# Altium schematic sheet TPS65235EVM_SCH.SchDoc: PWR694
size 431 x 279 mm; Date: Not shown in title block; ApprovedBy: Not shown in title block; CheckedBy: Not shown in title block; Author: Not shown in title block; CompanyName: Not shown in title block; DrawnBy: Junjie Mai; Engineer: Junjie Mai; Organization: Not shown in title block; Address1: Not shown in title block; Address2: Not shown in title block; Address3: Not shown in title block; Address4: Not shown in title block; DocumentNumber: 1; Revision: Use project parameter SCH_Rev; SheetNumber: 1; SheetTotal: 2; PageSetup: Record=PageOptions¦CenterHorizontal=True¦CenterVertical=True¦PrintScale=0.64¦XCorrection=1.00¦YCorrection=1.00¦PrintKind=0¦BorderSize=5000000¦LeftOffset=0¦BottomOffset=0¦Orientation=2¦PaperLength=1000¦PaperWidth=1000¦Scale=100¦PaperSource=15¦PrintQuality=600¦MediaType=1¦DitherType=10¦PrintScaleMode=1¦PaperKind=Letter
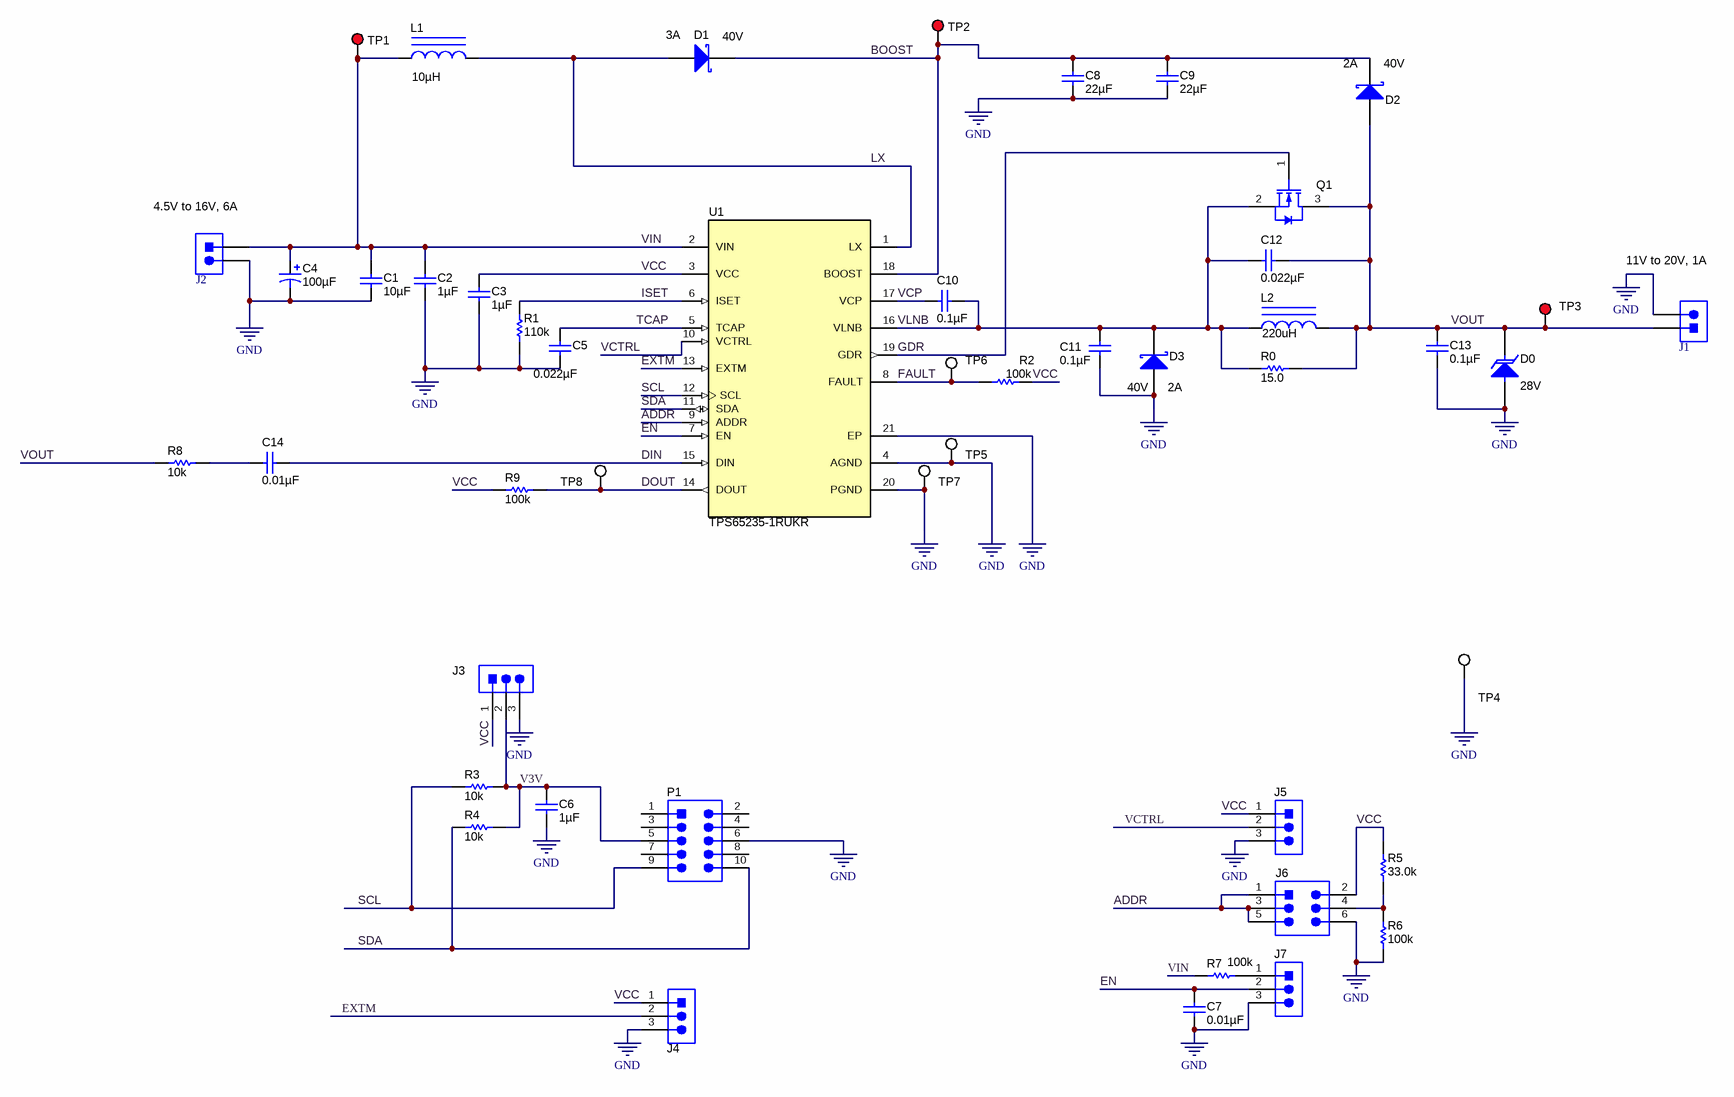
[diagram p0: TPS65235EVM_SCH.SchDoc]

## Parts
C1  ValueDisplayed: 10µF  [1206]  (hidden comment: GRM31CR61E106KA12L)
C2  ValueDisplayed: 1µF  [0603]  (hidden comment: GRM188R61E105KA12D)
C3  ValueDisplayed: 1µF  [0603]  (hidden comment: GRM188R61E105KA12D)
C4  ValueDisplayed: 100µF  [CAPPR250W50D630H1120]  (hidden comment: EEU-EB1E101S)
C5  ValueDisplayed: 0.022µF  [0603]  (hidden comment: GRM188R71H223KA01D)
C6  ValueDisplayed: 1µF  [0603]  (hidden comment: GRM188R61E105KA12D)
C7  ValueDisplayed: 0.01µF  [0603]  (hidden comment: GRM188R71H103KA01D)
C8  ValueDisplayed: 22µF  [1206_180]  (hidden comment: C3216X5R1V226M160AC)
C9  ValueDisplayed: 22µF  [1206_180]  (hidden comment: C3216X5R1V226M160AC)
C10  ValueDisplayed: 0.1µF  [0603]  (hidden comment: 0603YC104JAT2A)
C11  ValueDisplayed: 0.1µF  [0603]  (hidden comment: GRM188R71H104KA93D)
C12  ValueDisplayed: 0.022µF  [0603]  (hidden comment: GRM188R71H223KA01D)
C13  ValueDisplayed: 0.1µF  [0603]  (hidden comment: GRM188R71H104KA93D)
C14  ValueDisplayed: 0.01µF  [0603]  (hidden comment: GRM188R71H103KA01D)
D0  value 28V  [SMC]  (hidden comment: SMCJ28A)
D1  value 40V  Value1: 3A  [SMA]  (hidden comment: B340A-13-F)
D2  value 40V  Value1: 2A  [SMA]  (hidden comment: B240A-13-F)
D3  value 40V  Value1: 2A  [SMA]  (hidden comment: B240A-13-F)
J1  ED555/2DS  [TERM_BLK_ED555-2DS]  (value not drawn)
J2  ED555/2DS  [TERM_BLK_ED555-2DS]  (value not drawn)
J3  TSW-103-07-G-S  [TSW-103-07-G-S]  (value not drawn)
J4  TSW-103-07-G-S  [TSW-103-07-G-S]  (value not drawn)
J5  TSW-103-07-G-S  [TSW-103-07-G-S]  (value not drawn)
J6  TSW-103-07-G-D  [TSW-103-07-G-D]  (value not drawn)
J7  TSW-103-07-G-S  [TSW-103-07-G-S]  (value not drawn)
L1  ValueDisplayed: 10µH  [CLF10040]  (hidden comment: CLF10040T-100M)
L2  value 220uH  [SLF12565]  (hidden comment: SLF12565T-221M1R0-PF)
P1  XG4C-1031  [OMRON_XG4C-1031]  (value not drawn)
Q1  SI2316BDS-T1-E3  [SOT-23]  (value not drawn)
R0  ValueDisplayed: 15.0  [1206]  (hidden comment: CRCW120615R0FKEA)
R1  ValueDisplayed: 110k  [0603]  (hidden comment: CRCW0603110KFKEA)
R2  ValueDisplayed: 100k  [0603]  (hidden comment: CRCW0603100KFKEA)
R3  ValueDisplayed: 10k  [0603]  (hidden comment: CRCW060310K0JNEA)
R4  ValueDisplayed: 10k  [0603]  (hidden comment: CRCW060310K0JNEA)
R5  ValueDisplayed: 33.0k  [0603]  (hidden comment: CRCW060333K0FKEA)
R6  ValueDisplayed: 100k  [0603]  (hidden comment: CRCW0603100KFKEA)
R7  ValueDisplayed: 100k  [0603]  (hidden comment: CRCW0603100KFKEA)
R8  ValueDisplayed: 10k  [0603]  (hidden comment: CRCW060310K0JNEA)
R9  ValueDisplayed: 100k  [0603]  (hidden comment: CRCW0603100KFKEA)
TP1  5010  [Keystone5010]  (value not drawn)
TP2  5010  [Keystone5010]  (value not drawn)
TP3  5010  [Keystone5010]  (value not drawn)
TP4  5012  [Keystone5012]  (value not drawn)
TP5  5012  [Keystone5012]  (value not drawn)
TP6  5012  [Keystone5012]  (value not drawn)
TP7  5012  [Keystone5012]  (value not drawn)
TP8  5012  [Keystone5012]  (value not drawn)
U1  TPS65235-1RUKR  [RUK0020B]

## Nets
GND: C1.2 C2.2 C3.2 C4.2(-) C5.1 C6.2 C7.2 C8.2 C9.2 C11.2 C13.2 D0.2(A) D3.2(A) J1.2 J2.2 J3.3 J4.3 J5.3 J6.6 J7.3 P1.6 R1.1 R6.1 TP4.1 TP5.1 TP7.1 U1.4(AGND) U1.20(PGND) U1.21(EP)
ADDR: J6.1 J6.3 J6.5 U1.9(ADDR)
BOOST: C8.1 C9.1 D1.1(K) D2.1(K) TP2.1 U1.18(BOOST)
DIN: C14.1 U1.15(DIN)
DOUT: R9.2 TP8.1 U1.14(DOUT)
EN: C7.1 J7.2 U1.7(EN)
EXTM: J4.2 U1.13(EXTM)
FAULT: R2.1 TP6.1 U1.8(FAULT)
GDR: Q1.1(G) U1.19(GDR)
ISET: R1.2 U1.6(ISET)
LX: D1.2(A) L1.2 U1.1(LX)
SCL: P1.9 R3.2 U1.12(SCL)
SDA: P1.10 R4.2 U1.11(SDA)
TCAP: C5.2 U1.5(TCAP)
V3V: C6.1 J3.2 P1.5 R3.1 R4.1
VCC: C3.1 J3.1 J4.1 J5.1 J6.2 R2.2 R5.2 R9.1 U1.3(VCC)
VCP: C10.1 U1.17(VCP)
VCTRL: J5.2 U1.10(VCTRL)
VIN: C1.1 C2.1 C4.1(+) J2.1 L1.1 R7.2 TP1.1 U1.2(VIN)
VLNB: C10.2 C11.1 C12.1 D3.1(K) L2.1 Q1.2(S) R0.2 U1.16(VLNB)
VOUT: C12.2 C13.1 D0.1(K) D2.2(A) J1.1 L2.2 Q1.3(D) R0.1 R8.2 TP3.1
NetC14_2: C14.2 R8.1
NetJ6_4: J6.4 R5.1 R6.2
NetJ7_1: J7.1 R7.1

Not connected (* = marked no-connect by the designer): P1 1 2 3 4 7 8

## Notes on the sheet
- (near J2) 4.5V to 16V, 6A
- (near J1) 11V to 20V, 1A

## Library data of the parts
C1 = GRM31CR61E106KA12L: CAP, CERM, 10 µF, 25 V, +/- 10%, X5R, 1206; Manufacturer: MuRata; Polarized: N; CompType: Capacitor; Value: 10uF; U/M: EA; Cap_F: 0.00001; Tolerance_%: 10; ESR_ohm: 0.004; Value1: 0.004 ohm; VDC_V: 25; Value2: 25V; TaMin_C: -55; TaMax_C: 85; AEC Category: Q200
C2 C3 C6 = GRM188R61E105KA12D: CAP, CERM, 1 µF, 25 V, +/- 10%, X5R, 0603; Manufacturer: MuRata; Polarized: N; CompType: Capacitor; Value: 1uF; U/M: EA; Cap_F: 0.000001; Tolerance_%: 10; Value1: Unknown; VDC_V: 25; Value2: 25V; TaMin_C: -55; TaMax_C: 85; AEC Category: Q200
C4 = EEU-EB1E101S: CAP, AL, 100 µF, 25 V, +/- 20%, TH; Manufacturer: Panasonic; Polarized: Y; CompType: Capacitor; Value: 100uF; U/M: EA; Cap_F: 0.0001; Tolerance_%: 20; Value1: Unknown; VDC_V: 25; Value2: 25V; IRMS_A: 0.095; TaMin_C: -40; TaMax_C: 105; Cap_Case: Radial 6.3x11.2; AEC Category: Q200; AEC Qualified: N
C5 C12 = GRM188R71H223KA01D: CAP, CERM, 0.022 µF, 50 V, +/- 10%, X7R, 0603; Manufacturer: MuRata; Polarized: N; CompType: Capacitor; Value: 0.022uF; U/M: EA; Cap_F: 0.000000022; Tolerance_%: 10; Value1: Unknown; VDC_V: 50; Value2: 50V; TaMin_C: -55; TaMax_C: 125; AEC Category: Q200
C7 C14 = GRM188R71H103KA01D: CAP, CERM, 0.01 µF, 50 V, +/- 10%, X7R, 0603; Manufacturer: MuRata; Polarized: N; CompType: Capacitor; Value: 0.01uF; U/M: EA; Cap_F: 0.00000001; Tolerance_%: 10; Value1: Unknown; VDC_V: 50; Value2: 50V; TaMin_C: -55; TaMax_C: 125; AEC Category: Q200
C8 C9 = C3216X5R1V226M160AC: CAP, CERM, 22 µF, 35 V, +/- 20%, X5R, 1206; Manufacturer: TDK; Polarized: N; CompType: Capacitor; Value: 22uF; U/M: EA; Cap_F: 0.000022; Tolerance_%: 20; ESR_ohm: 0.002398; Value1: 0.002398 ohm; VDC_V: 35; Value2: 35V; IRMS_A: 4.68507; TaMin_C: -55; TaMax_C: 85; AEC Category: Q200; SizeArea_mm2: 5.12; SizeAreaWB_mm2: 10.92; SizeX_mm: 3.2; SizeY_mm: 1.6; SizeZ_mm: 1.8
C10 = 0603YC104JAT2A: CAP, CERM, 0.1 µF, 16 V, +/- 5%, X7R, 0603; Manufacturer: AVX; Polarized: N; CompType: Capacitor; Value: 0.1uF; U/M: EA; Cap_F: 0.0000001; Tolerance_%: 5; ESR_ohm: 0.039; Value1: 0.039 ohm; VDC_V: 16; Value2: 16V; TaMin_C: -55; TaMax_C: 125; AEC Category: Q200
C11 C13 = GRM188R71H104KA93D: CAP, CERM, 0.1 µF, 50 V, +/- 10%, X7R, 0603; Manufacturer: MuRata; Polarized: N; CompType: Capacitor; Value: 0.1uF; U/M: EA; Cap_F: 0.0000001; Tolerance_%: 10; Value1: Unknown; VDC_V: 50; Value2: 50V; TaMin_C: -55; TaMax_C: 125; AEC Category: Q200
D0 = SMCJ28A: Diode, TVS, Uni, 28 V, 1500 W, SMC; Manufacturer: Fairchild Semiconductor; U/M: EA; Value1: 1500W; Vr_V: 28; Power_W: 1500; AEC Category: Q101
D1 = B340A-13-F: Diode, Schottky, 40 V, 3 A, SMA; Manufacturer: Diodes Inc.; U/M: EA; Vf_V: 0.5; Value2: 0.5V; Io_A: 3; Vr_V: 40; TJmax_C: 125; RJC_CperW: 25; AEC Category: Q101
D2 D3 = B240A-13-F: Diode, Schottky, 40 V, 2 A, SMA; Manufacturer: Diodes Inc.; U/M: EA; Vf_V: 0.5; Value2: 0.5V; Io_A: 2; Vr_V: 40; TJmax_C: 150; RJC_CperW: 20; AEC Category: Q101
J1 J2 = ED555/2DS: Terminal Block, 6A, 3.5mm Pitch, 2-Pos, TH; Manufacturer: On-Shore Technology; SymbolCreator: a0412235; CompType: Connector; U/M: EA
J3-J5 J7 = TSW-103-07-G-S: Header, 100mil, 3x1, Gold, TH; Manufacturer: Samtec; SymbolCreator: a0799628; U/M: EA
J6 = TSW-103-07-G-D: Header, 100mil, 3x2, Gold, TH; Manufacturer: Samtec; SymbolCreator: a0412235; U/M: EA
L1 = CLF10040T-100M: Inductor, Shielded, Ferrite, 10 µH, 4 A, 0.0312 ohm, SMD; Manufacturer: TDK; Value: 10uH; Ind_H: 10.0E-6; Imax_A: 4; Irms: 3.3A @ 30C rise; Isat: 4A @ 10% inductance drop; DCR_ohm: 0.0312; Value2: 4A; AEC Category: Q200
L2 = SLF12565T-221M1R0-PF: Inductor, Shielded, Ferrite, 220 µH, 1.2 A, 0.273 ohm, SMD; Manufacturer: TDK; Ind_H: 220.0E-6; ValueDisplayed: 220µH; Imax_A: 1.2; Irms: 1.2A @ 40C rise; Isat: 1A @ 10% inductance drop; DCR_ohm: 0.273; Value2: 1.2A; AEC Category: Q200
P1 = XG4C-1031: Header (shrouded), 100mil, 5x2, Gold, TH; Manufacturer: Omron Electronic Components; SymbolCreator: a0412235; U/M: EA
Q1 = SI2316BDS-T1-E3: MOSFET, N-CH, 30 V, 4.5 A, SOT-23; Manufacturer: Vishay-Siliconix; Alternate Manufacturer: None; U/M: EA; ChType: N; Value: 30V; VdsMax_V: 30; Value1: 0.08 ohm; Rdson45_ohm: 0.08; Value2: 3.16 nC; QgTyp_nC: 3.16; Vgs_V: 20; IdsMax_A: 4.5; AEC Category: Q101
R0 = CRCW120615R0FKEA: RES, 15.0, 1%, 0.25 W, 1206; Manufacturer: Vishay-Dale; Value: 15.0; CompType: Resistor; Res_ohm: 15; Value_Code: 15R0; Tolerance_%: 1; Power_W: 0.25; Value2: 0.25W; VDC_V: 200; TempCo: 100 ppm/C; EIA_Code: E96; U/M: EA; AEC Category: Q200
R1 = CRCW0603110KFKEA: RES, 110 k, 1%, 0.1 W, 0603; Manufacturer: Vishay-Dale; Value: 110k; CompType: Resistor; Res_ohm: 110000; Tolerance_%: 1; Power_W: 0.1; Value2: 0.1W; VDC_V: 75; TempCo: 100 ppm/C; EIA_Code: E96; U/M: EA; AEC Category: Q200
R2 R6 R7 R9 = CRCW0603100KFKEA: RES, 100 k, 1%, 0.1 W, 0603; Manufacturer: Vishay-Dale; Value: 100k; CompType: Resistor; Res_ohm: 100000; Tolerance_%: 1; Power_W: 0.1; Value2: 0.1W; VDC_V: 75; TempCo: 100 ppm/C; EIA_Code: E96; U/M: EA; AEC Category: Q200
R3 R4 R8 = CRCW060310K0JNEA: RES, 10 k, 5%, 0.1 W, 0603; Manufacturer: Vishay-Dale; Value: 10k; CompType: Resistor; Res_ohm: 10000; Value_Code: 10k0; Tolerance_%: 5; Power_W: 0.1; Value2: 0.1W; VDC_V: 75; TempCo: 200 ppm/C; EIA_Code: E24; U/M: EA; AEC Category: Q200
R5 = CRCW060333K0FKEA: RES, 33.0 k, 1%, 0.1 W, 0603; Manufacturer: Vishay-Dale; Value: 33.0k; CompType: Resistor; Res_ohm: 33000; Value_Code: 33k0; Tolerance_%: 1; Power_W: 0.1; Value2: 0.1W; VDC_V: 75; TempCo: 100 ppm/C; U/M: EA; AEC Category: Q200
TP1-TP3 = 5010: Test Point, Multipurpose, Red, TH; Manufacturer: Keystone; CompType: Test Point Loop; U/M: EA
TP4-TP8 = 5012: Test Point, Multipurpose, White, TH; Manufacturer: Keystone; CompType: Test Point Loop; U/M: EA
U1 = TPS65235-1RUKR: LNB VOLTAGE REGULATOR WITH I2C INTERFACE, RUK0020B; Manufacturer: Texas Instruments; Alternate PartNumber: TPS65235-1RUKT; SymbolCreator: Altium; CompType: IC; U/M: EA; SizeArea_mm2: 9; SizeAreaWB_mm2: 16; SizeX_mm: 3; SizeZ_mm: 0.8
